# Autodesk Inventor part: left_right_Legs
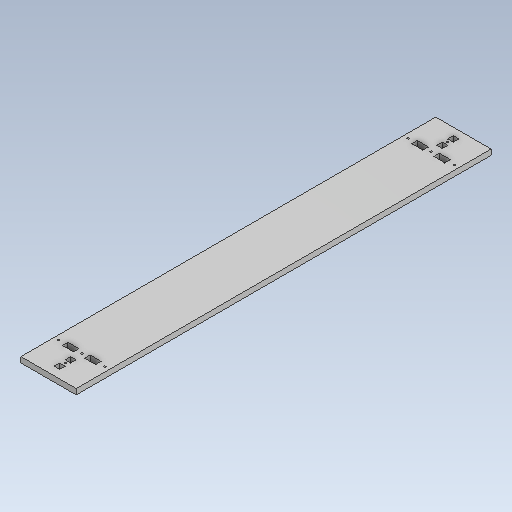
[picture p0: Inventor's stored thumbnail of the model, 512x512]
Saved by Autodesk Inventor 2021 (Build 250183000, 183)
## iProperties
Created: 2026-10
Part Number: left_right_Legs
Material: Steel
Document SubType Name: Modeling
Designer: hp
Density: 7.85 g/cm^3
Appearance: Default
Author: hp
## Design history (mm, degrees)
feature "Body1"
body "Solid1"
